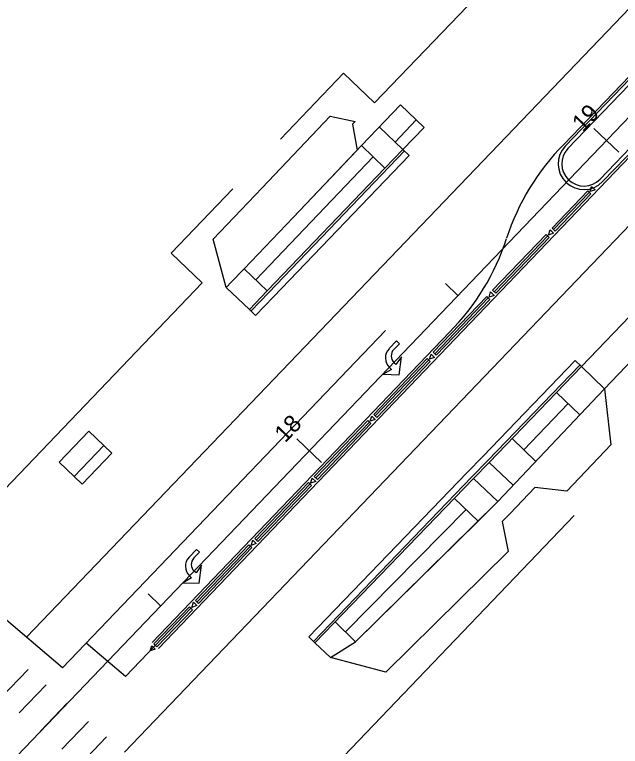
# Model space of a CAD drawing. Extents: x 2377903 to 2496516, y 664638 to 732785.
# Drawn here: x 2378395.6 to 2378536.6, y 730603.2 to 730773.5 of the extents above; entities that cross this region are included whole.
import ezdxf

# ---------------------------------------------------------------- set-up
doc = ezdxf.new("R2010")
doc.units = 0
for name, color, linetype in [('ALG_CL_BLUE_Horiz', 7, 'Continuous'), ('ALG_CL_BLUE_Horiz-Stationing', 7, 'Continuous'), ('Default', 7, 'Continuous'), ('DES_ROADWAY_Approach', 7, 'Continuous'), ('DES_ROADWAY_Concrete-Pavement', 7, 'Continuous'), ('DES_ROADWAY_Curb-Back', 7, 'Continuous'), ('DES_ROADWAY_Curb-Face', 7, 'Continuous'), ('DES_ROADWAY_Curb-Face-LINE STYLE', 7, 'Continuous'), ('DES_ROADWAY_Edge-of-Pavement', 7, 'Continuous'), ('DES_ROADWAY_Sidewalk', 7, 'Continuous'), ('ROW_P_PUA', 7, 'Continuous'), ('TRAF_PAVEMARK_Arrows', 7, 'Continuous'), ('TRAF_PAVEMARK_Stop-Bar', 7, 'Continuous'), ('TRAF_PAVEMARK_White_8-IN', 7, 'Continuous'), ('TRAF_PAVEMARK_White_SKIP 12-38', 7, 'Continuous'), ('TRAF_PAVEMARK_Yellow', 7, 'Continuous'), ('TRAF_PAVEMARK_Yellow-DBL YELLOW', 7, 'Continuous'), ('TRAF_WORKZONE_Drum', 7, 'Continuous')]:
    doc.layers.add(name, color=color, linetype=linetype)

msp = doc.modelspace()

# ---------------------------------------------------------------- linework, layer by layer
at = {"layer": 'ALG_CL_BLUE_Horiz'}
msp.add_line((2378375.43, 730579.33), (2378840.27, 731064.93), dxfattribs=at)
at = {"layer": 'ALG_CL_BLUE_Horiz-Stationing'}
for p, q in [((2378530.42, 730747.03), (2378536.2, 730741.5)), ((2378495.85, 730710.91), (2378498.74, 730708.14)), ((2378461.27, 730674.79), (2378467.05, 730669.26)), ((2378426.7, 730638.67), (2378429.59, 730635.91))]:
    msp.add_line(p, q, dxfattribs=at)
at = {"layer": 'Default'}
for p, q in [((2378451.72, 730711.79), (2378479.05, 730740.43)), ((2378514.13, 730672.21), (2378524.4, 730682.98)), ((2378472.58, 730629.86), (2378500.7, 730658.31))]:
    msp.add_line(p, q, dxfattribs=at)
at = {"layer": 'DES_ROADWAY_Approach'}
for p, q in [((2378532.77, 730686.32), (2378532.89, 730686.46)), ((2378508.06, 730660.19), (2378508.06, 730660.19)), ((2378508.06, 730660.19), (2378508.06, 730660.19))]:
    msp.add_line(p, q, dxfattribs=at)
for points in [[(2378469.05, 730749.93), (2378474.86, 730748.64), (2378474.28, 730748.01), (2378475.3, 730741.99), (2378460.46, 730726.31), (2378449.02, 730714.37), (2378446.06, 730711.3), (2378444.87, 730710.05), (2378441.8, 730721.29), (2378453.22, 730733.2)], [(2378484.14, 730743.87), (2378489.08, 730749.02), (2378490.89, 730747.29), (2378485.95, 730742.14)], [(2378534.33, 730673.42), (2378524.11, 730662.61), (2378516.63, 730663.43), (2378510.95, 730657.42), (2378509.03, 730655.53), (2378510.48, 730648.53), (2378482, 730620.43), (2378469.12, 730623.86), (2378474.98, 730627.55), (2378508.09, 730660.21), (2378532.77, 730686.32), (2378532.89, 730686.46)], [(2378418.28, 730671.44), (2378411.36, 730664.22), (2378409.51, 730666), (2378416.43, 730673.21)]]:
    msp.add_lwpolyline(points, close=True, dxfattribs=at)
at = {"layer": 'DES_ROADWAY_Concrete-Pavement'}
for p, q in [((2378524.37, 730742.39), (2378682.32, 730907.39)), ((2378689.78, 730900.25), (2378531.83, 730735.24))]:
    msp.add_line(p, q, dxfattribs=at)
msp.add_arc((2378528.1, 730738.81), 5.17, 136.2512, 316.2512, dxfattribs=at)
at = {"layer": 'DES_ROADWAY_Curb-Back'}
for p, q in [((2378524.37, 730742.39), (2378682.32, 730907.39)), ((2378531.83, 730735.24), (2378689.78, 730900.25)), ((2378521.04, 730723.48), (2378529.33, 730732.15)), ((2378507.21, 730709.03), (2378519.65, 730722.04)), ((2378493.38, 730694.59), (2378505.82, 730707.59)), ((2378479.55, 730680.14), (2378491.99, 730693.14)), ((2378465.72, 730665.69), (2378478.16, 730678.69)), ((2378451.89, 730651.24), (2378464.33, 730664.25)), ((2378438.06, 730636.8), (2378450.5, 730649.8)), ((2378428.37, 730626.68), (2378436.67, 730635.35))]:
    msp.add_line(p, q, dxfattribs=at)
for points in [[(2378450.27, 730704.88), (2378454.42, 730709.21), (2378481.8, 730737.81), (2378485.95, 730742.14)], [(2378465.5, 730627.29), (2378502.36, 730665.57), (2378506, 730669.31), (2378527.48, 730691.63)]]:
    msp.add_lwpolyline(points, dxfattribs=at)
msp.add_arc((2378528.1, 730738.81), 5.17, 136.2512, 316.2512, dxfattribs=at)
at = {"layer": 'DES_ROADWAY_Curb-Face'}
for p, q in [((2378520.67, 730723.83), (2378528.97, 730732.5)), ((2378521.4, 730723.14), (2378529.69, 730731.8)), ((2378528.97, 730732.5), (2378529.69, 730731.8)), ((2378520.67, 730723.83), (2378521.4, 730723.14)), ((2378506.84, 730709.38), (2378519.29, 730722.38)), ((2378507.57, 730708.69), (2378520.01, 730721.69)), ((2378519.29, 730722.38), (2378520.01, 730721.69)), ((2378506.84, 730709.38), (2378507.57, 730708.69)), ((2378493.01, 730694.93), (2378505.46, 730707.94)), ((2378505.46, 730707.94), (2378506.18, 730707.24)), ((2378493.74, 730694.24), (2378506.18, 730707.24)), ((2378493.01, 730694.93), (2378493.74, 730694.24)), ((2378479.18, 730680.48), (2378491.63, 730693.49)), ((2378479.91, 730679.79), (2378492.35, 730692.8)), ((2378491.63, 730693.49), (2378492.35, 730692.8)), ((2378479.18, 730680.48), (2378479.91, 730679.79)), ((2378465.35, 730666.04), (2378477.8, 730679.04)), ((2378477.8, 730679.04), (2378478.52, 730678.35)), ((2378466.08, 730665.35), (2378478.52, 730678.35)), ((2378465.35, 730666.04), (2378466.08, 730665.35)), ((2378451.52, 730651.59), (2378463.97, 730664.59)), ((2378452.25, 730650.9), (2378464.69, 730663.9)), ((2378463.97, 730664.59), (2378464.69, 730663.9)), ((2378451.52, 730651.59), (2378452.25, 730650.9)), ((2378437.69, 730637.14), (2378450.14, 730650.14)), ((2378450.14, 730650.14), (2378450.86, 730649.45)), ((2378438.42, 730636.45), (2378450.86, 730649.45)), ((2378437.69, 730637.14), (2378438.42, 730636.45)), ((2378428.01, 730627.03), (2378436.31, 730635.7)), ((2378428.74, 730626.34), (2378437.03, 730635.01)), ((2378436.31, 730635.7), (2378437.03, 730635.01)), ((2378428.01, 730627.03), (2378428.74, 730626.34))]:
    msp.add_line(p, q, dxfattribs=at)
at = {"layer": 'DES_ROADWAY_Curb-Face-LINE STYLE'}
for points in [[(2378450.63, 730704.53), (2378454.78, 730708.86), (2378486.31, 730741.8)], [(2378527.12, 730691.97), (2378505.64, 730669.66), (2378502, 730665.92), (2378465.14, 730627.64)]]:
    msp.add_lwpolyline(points, dxfattribs=at)
at = {"layer": 'DES_ROADWAY_Edge-of-Pavement'}
for p, q in [((2378523.76, 730742.96), (2378681.72, 730907.97)), ((2378532.43, 730734.67), (2378690.38, 730899.67)), ((2378485.95, 730742.14), (2378487.39, 730740.76)), ((2378451.71, 730703.49), (2378450.27, 730704.88)), ((2378526.04, 730693.02), (2378527.48, 730691.63)), ((2378464.06, 730628.68), (2378465.5, 730627.29))]:
    msp.add_line(p, q, dxfattribs=at)
for points in [[(2378487.39, 730740.76), (2378455.86, 730707.83), (2378451.71, 730703.49)], [(2378526.04, 730693.02), (2378504.56, 730670.7), (2378500.92, 730666.96), (2378464.06, 730628.68)]]:
    msp.add_lwpolyline(points, dxfattribs=at)
msp.add_arc((2378528.1, 730738.81), 6, 136.2512, 316.2512, dxfattribs=at)
at = {"layer": 'DES_ROADWAY_Sidewalk'}
for p, q in [((2378527.48, 730691.63), (2378603, 730770.48)), ((2378485.4, 730752.55), (2378476.31, 730743.06)), ((2378485.4, 730752.55), (2378489.08, 730749.02)), ((2378480.46, 730747.39), (2378485.95, 730742.14)), ((2378460.46, 730726.31), (2378476.31, 730743.06)), ((2378476.31, 730743.06), (2378481.8, 730737.81)), ((2378449.02, 730714.37), (2378460.46, 730726.31)), ((2378446.06, 730711.3), (2378449.02, 730714.37)), ((2378449.02, 730714.37), (2378454.42, 730709.21)), ((2378444.87, 730710.05), (2378446.06, 730711.3)), ((2378444.87, 730710.05), (2378450.27, 730704.88)), ((2378527.48, 730691.63), (2378532.89, 730686.46)), ((2378508.09, 730660.21), (2378532.77, 730686.32)), ((2378527.13, 730680.36), (2378521.68, 730685.6)), ((2378412.94, 730676.56), (2378406.04, 730669.32)), ((2378416.43, 730673.21), (2378412.94, 730676.56)), ((2378516.9, 730669.54), (2378511.36, 730674.88)), ((2378409.51, 730666), (2378416.43, 730673.21)), ((2378409.51, 730666), (2378406.04, 730669.32)), ((2378506, 730669.31), (2378511.65, 730663.98)), ((2378502.36, 730665.57), (2378508.06, 730660.19)), ((2378503.46, 730655.65), (2378497.93, 730660.97)), ((2378503.46, 730655.65), (2378508.09, 730660.21)), ((2378474.98, 730627.55), (2378503.46, 730655.65)), ((2378474.98, 730627.55), (2378470.19, 730632.16)), ((2378469.12, 730623.86), (2378474.98, 730627.55)), ((2378465.5, 730627.29), (2378469.12, 730623.86))]:
    msp.add_line(p, q, dxfattribs=at)
msp.add_lwpolyline([(2378532.77, 730686.32), (2378606.65, 730763.63), (2378608.17, 730765.16)], dxfattribs=at)
at = {"layer": 'ROW_P_PUA'}
for p, q in [((2378479.37, 730752.99), (2378560.28, 730837.5)), ((2378472.15, 730759.9), (2378457.46, 730744.56)), ((2378472.15, 730759.9), (2378479.37, 730752.99)), ((2378446.4, 730733), (2378432.04, 730718)), ((2378432.04, 730718), (2378439.26, 730711.09)), ((2378370.59, 730639.35), (2378439.26, 730711.09)), ((2378442.81, 730570.18), (2378525.84, 730656.92))]:
    msp.add_line(p, q, dxfattribs=at)
at = {"layer": 'TRAF_PAVEMARK_Arrows'}
for p, q in [((2378484.47, 730697.57), (2378482.75, 730695.78)), ((2378485.14, 730696.93), (2378484.47, 730697.57)), ((2378483.85, 730695.59), (2378485.14, 730696.93)), ((2378484.36, 730692.08), (2378483.92, 730692.51)), ((2378485.64, 730693.87), (2378484.36, 730692.08)), ((2378485.07, 730689.68), (2378485.64, 730693.87)), ((2378483.29, 730690.96), (2378481.34, 730689.83)), ((2378482.84, 730691.39), (2378483.29, 730690.96)), ((2378481.34, 730689.83), (2378485.07, 730689.68)), ((2378437.95, 730649.05), (2378436.23, 730647.26)), ((2378437.33, 730647.06), (2378438.62, 730648.41)), ((2378438.62, 730648.41), (2378437.95, 730649.05)), ((2378439.12, 730645.34), (2378437.84, 730643.56)), ((2378438.55, 730641.16), (2378439.12, 730645.34)), ((2378436.32, 730642.87), (2378436.77, 730642.44)), ((2378437.84, 730643.56), (2378437.39, 730643.99)), ((2378436.77, 730642.44), (2378434.82, 730641.3)), ((2378434.82, 730641.3), (2378438.55, 730641.16))]:
    msp.add_line(p, q, dxfattribs=at)
for centre, radius in [((2378484.99, 730693.63), 3.1), ((2378485.42, 730694.08), 2.17), ((2378438.47, 730645.11), 3.1), ((2378438.9, 730645.56), 2.17)]:
    msp.add_arc(centre, radius, 136.2016, 226.2016, dxfattribs=at)
at = {"layer": 'TRAF_PAVEMARK_Stop-Bar'}
for p, q in [((2378406.76, 730621.46), (2378388.24, 730637.27)), ((2378421.44, 730619.44), (2378412.3, 730627.24)), ((2378392.53, 730614.54), (2378398.76, 730621.05)), ((2378396.72, 730610.97), (2378402.95, 730617.48)), ((2378401.67, 730606.74), (2378407.9, 730613.25)), ((2378406.62, 730602.51), (2378412.85, 730609.02)), ((2378410.81, 730598.93), (2378417.04, 730605.44))]:
    msp.add_line(p, q, dxfattribs=at)
at = {"layer": 'TRAF_PAVEMARK_White_8-IN'}
msp.add_line((2378406.76, 730621.46), (2378481.94, 730699.99), dxfattribs=at)
at = {"layer": 'TRAF_PAVEMARK_White_SKIP 12-38'}
for p, q in [((2378398.38, 730628.61), (2378793.36, 731041.22)), ((2378421.23, 730601.86), (2378814.84, 731013.05))]:
    msp.add_line(p, q, dxfattribs=at)
at = {"layer": 'TRAF_PAVEMARK_Yellow'}
for p, q in [((2378523.4, 730743.31), (2378785.05, 731016.64)), ((2378429.1, 730625.99), (2378690.75, 730899.32)), ((2378427.65, 730627.38), (2378496.8, 730699.61))]:
    msp.add_line(p, q, dxfattribs=at)
for centre, start, end in [((2378562.23, 730704.7), 135.1621, 162.1744), ((2378457.97, 730738.22), 315.1621, 342.1744)]:
    msp.add_arc(centre, 54.76, start, end, dxfattribs=at)
at = {"layer": 'TRAF_PAVEMARK_Yellow-DBL YELLOW'}
msp.add_line((2378421.44, 730619.44), (2378428.37, 730626.68), dxfattribs=at)
at = {"layer": 'TRAF_WORKZONE_Drum'}
for points in [[(2378529.51, 730732.33), (2378529.88, 730733.53), (2378530.69, 730732.75)], [(2378519.83, 730722.22), (2378520.2, 730723.42), (2378521.01, 730722.64)], [(2378506, 730707.77), (2378506.37, 730708.97), (2378507.18, 730708.19)], [(2378492.17, 730693.32), (2378492.54, 730694.52), (2378493.35, 730693.75)], [(2378478.34, 730678.87), (2378478.71, 730680.08), (2378479.52, 730679.3)], [(2378464.51, 730664.43), (2378464.88, 730665.63), (2378465.69, 730664.85)], [(2378450.68, 730649.98), (2378451.05, 730651.18), (2378451.86, 730650.4)], [(2378436.85, 730635.53), (2378437.22, 730636.73), (2378438.03, 730635.96)], [(2378427.16, 730625.42), (2378427.54, 730626.62), (2378428.35, 730625.84)]]:
    msp.add_lwpolyline(points, close=True, dxfattribs=at)

# ---------------------------------------------------------------- texts
at = {"layer": 'ALG_CL_BLUE_Horiz-Stationing'}
for s, p in [('19', (2378527.8, 730746.03)), ('18', (2378458.59, 730673.72))]:
    msp.add_text(s, height=4, rotation=46.2512, dxfattribs=at).set_placement(p)

doc.saveas('drawing.dxf')
